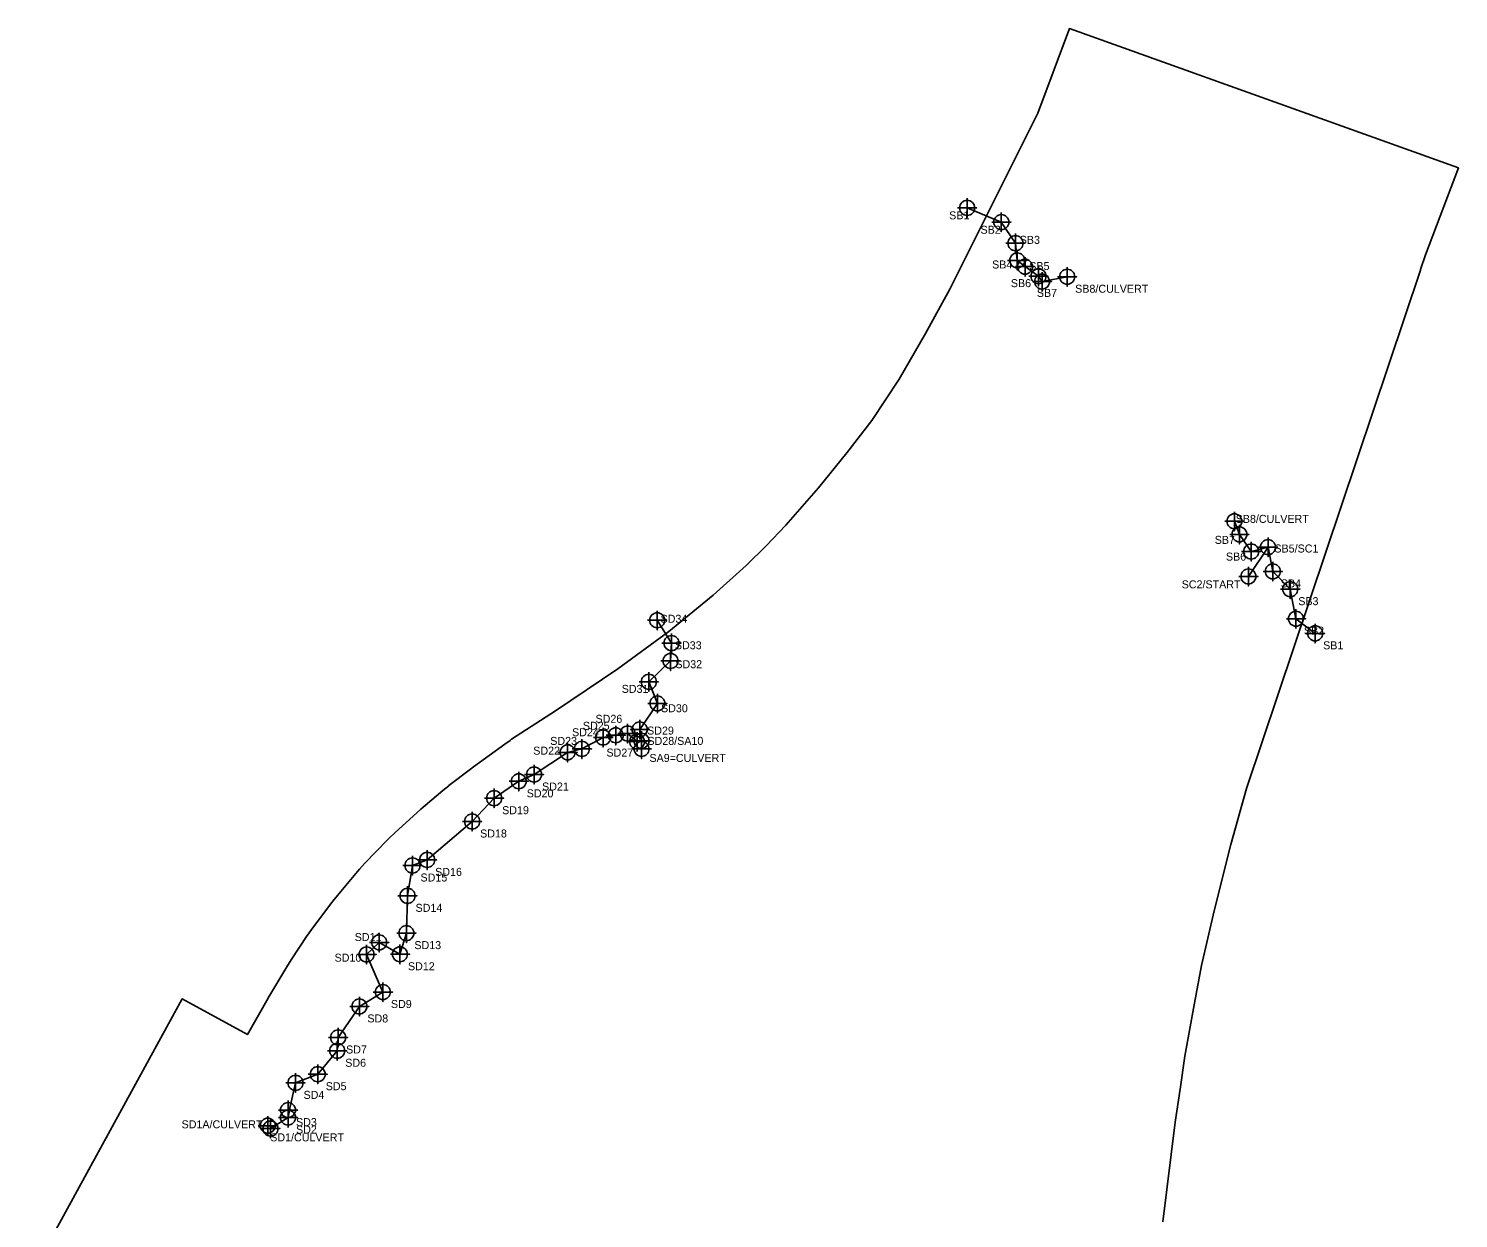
# Model space of a CAD drawing. Extents: x 2074690 to 2076562, y 742141 to 745115.
# Drawn here: x 2074775 to 2076562, y 743628 to 745115 of the extents above; entities that cross this region are included whole.
import ezdxf

# ---------------------------------------------------------------- set-up
doc = ezdxf.new("R2010")
doc.units = 0
for name, color, linetype in [('Default', 7, 'Continuous'), ('Exist Hydro Jurisdictional Stream or Body of Water Mitigable', 7, 'Continuous'), ('Exist Hydro Jurisdictional Stream or Body of Water Mitigable Cogo Comment', 7, 'Continuous'), ('Exist Hydro Jurisdictional Stream or Body of Water Mitigable Cogo Point CELL', 7, 'Continuous')]:
    doc.layers.add(name, color=color, linetype=linetype)

msp = doc.modelspace()

# ---------------------------------------------------------------- linework, layer by layer
at = {"layer": 'Default'}
msp.add_lwpolyline([(2074774.6, 743551.4), (2074966.7, 743902.2), (2075048, 743857.7), (2075048.2, 743858), (2075073.9, 743903.4), (2075074.6, 743904.6), (2075076, 743906.9), (2075097.2, 743942.5), (2075102.6, 743951.1), (2075122.9, 743981.6), (2075123, 743981.8), (2075129.3, 743990.7), (2075153.5, 744022.9), (2075154.8, 744024.6), (2075160.5, 744031.7), (2075185.5, 744061.4), (2075188.1, 744064.4), (2075195, 744071.8), (2075223.3, 744101), (2075225.4, 744103.1), (2075232.3, 744109.7), (2075264.9, 744139.3), (2075267.6, 744141.7), (2075270.2, 744144), (2075292.3, 744162.7), (2075299.7, 744168.6), (2075299.9, 744168.8), (2075327, 744189.5), (2075330.8, 744192.4), (2075369.8, 744220.8), (2075376.4, 744225.4), (2075378.3, 744226.7), (2075433, 744262.3), (2075511.1, 744314.7), (2075574.7, 744361.4), (2075630.3, 744406.7), (2075671.5, 744443.9), (2075696.4, 744468.4), (2075720.9, 744494.3), (2075762, 744541), (2075797.4, 744584.5), (2075828.3, 744624.9), (2075862.6, 744676.8), (2075895.5, 744733.6), (2075926, 744789.2), (2076035.8, 745009.1), (2076075.4, 745114.8), (2076561.5, 744940.7), (2076520.4, 744832.2), (2076514.2, 744813.8), (2076514, 744813.1), (2076296.7, 744165.4), (2076277.1, 744095.1), (2076256.5, 744012.5), (2076240.6, 743944.2), (2076230.6, 743890.5), (2076219.8, 743830.7), (2076213.7, 743789.4), (2076207.6, 743748.1), (2076192, 743623.9)], dxfattribs=at)
at = {"layer": 'Exist Hydro Jurisdictional Stream or Body of Water Mitigable'}
for points in [[(2075947.6, 744890.7), (2075990.3, 744872.9), (2076008, 744846.6), (2076010.2, 744825.1), (2076019.9, 744817.3), (2076036.8, 744805.3), (2076041.2, 744798.6), (2076072.6, 744804.7)], [(2076281.6, 744499.1), (2076287.8, 744482.8), (2076302.6, 744461.3), (2076323.6, 744466.8), (2076329.6, 744436.5), (2076351.4, 744414.3), (2076358.5, 744377.4), (2076382.5, 744359.1)], [(2076323.6, 744466.8), (2076299.1, 744430.2)], [(2075076.9, 743740.3), (2075098.8, 743754), (2075101.6, 743767.8), (2075108.2, 743797.4), (2075135.9, 743808.2), (2075160.3, 743837.5), (2075161.4, 743854.1), (2075188, 743892.9), (2075217.4, 743910.9), (2075197, 743957.8), (2075212.8, 743972.9), (2075238.7, 743958.1), (2075246.7, 743984.5), (2075248.2, 744031.1), (2075254.4, 744069), (2075272.7, 744076), (2075328.9, 744124), (2075356.4, 744153.1), (2075387.1, 744174.2), (2075406.3, 744182.7), (2075448.2, 744210.4), (2075466.1, 744214.7), (2075492.6, 744229), (2075508.4, 744231.7), (2075523.2, 744233.9), (2075535, 744223.8), (2075540.5, 744224.8), (2075538.3, 744239), (2075560.4, 744271.6), (2075549.8, 744298.5), (2075576.9, 744324.6), (2075578.1, 744346.9), (2075560.2, 744375.4)], [(2075540.5, 744224.8), (2075540.7, 744214.6)]]:
    msp.add_lwpolyline(points, dxfattribs=at)
at = {"layer": 'Exist Hydro Jurisdictional Stream or Body of Water Mitigable Cogo Point CELL'}
for points in [[(2075947.6, 744902.7), (2075947.6, 744878.7), (2075947.6, 744890.7), (2075959.6, 744890.7), (2075935.6, 744890.7)], [(2075990.3, 744884.9), (2075990.3, 744860.9), (2075990.3, 744872.9), (2076002.3, 744872.9), (2075978.3, 744872.9)], [(2076008, 744858.6), (2076008, 744834.6), (2076008, 744846.6), (2076020, 744846.6), (2075996, 744846.6)], [(2076010.2, 744837.1), (2076010.2, 744813.1), (2076010.2, 744825.1), (2076022.2, 744825.1), (2075998.2, 744825.1)], [(2076019.9, 744829.3), (2076019.9, 744805.3), (2076019.9, 744817.3), (2076031.9, 744817.3), (2076007.9, 744817.3)], [(2076036.8, 744817.3), (2076036.8, 744793.3), (2076036.8, 744805.3), (2076048.8, 744805.3), (2076024.8, 744805.3)], [(2076072.6, 744816.7), (2076072.6, 744792.7), (2076072.6, 744804.7), (2076084.6, 744804.7), (2076060.6, 744804.7)], [(2076041.2, 744810.6), (2076041.2, 744786.6), (2076041.2, 744798.6), (2076053.2, 744798.6), (2076029.2, 744798.6)], [(2076281.6, 744511.1), (2076281.6, 744487.1), (2076281.6, 744499.1), (2076293.6, 744499.1), (2076269.6, 744499.1)], [(2076287.8, 744494.8), (2076287.8, 744470.8), (2076287.8, 744482.8), (2076299.8, 744482.8), (2076275.8, 744482.8)], [(2076302.6, 744473.3), (2076302.6, 744449.3), (2076302.6, 744461.3), (2076314.6, 744461.3), (2076290.6, 744461.3)], [(2076323.6, 744478.8), (2076323.6, 744454.8), (2076323.6, 744466.8), (2076335.6, 744466.8), (2076311.6, 744466.8)], [(2076299.1, 744442.2), (2076299.1, 744418.2), (2076299.1, 744430.2), (2076311.1, 744430.2), (2076287.1, 744430.2)], [(2076329.6, 744448.5), (2076329.6, 744424.5), (2076329.6, 744436.5), (2076341.6, 744436.5), (2076317.6, 744436.5)], [(2076351.4, 744426.3), (2076351.4, 744402.3), (2076351.4, 744414.3), (2076363.4, 744414.3), (2076339.4, 744414.3)], [(2075560.2, 744387.4), (2075560.2, 744363.4), (2075560.2, 744375.4), (2075572.2, 744375.4), (2075548.2, 744375.4)], [(2076358.5, 744389.4), (2076358.5, 744365.4), (2076358.5, 744377.4), (2076370.5, 744377.4), (2076346.5, 744377.4)], [(2076382.5, 744371.1), (2076382.5, 744347.1), (2076382.5, 744359.1), (2076394.5, 744359.1), (2076370.5, 744359.1)], [(2075578.1, 744358.9), (2075578.1, 744334.9), (2075578.1, 744346.9), (2075590.1, 744346.9), (2075566.1, 744346.9)], [(2075576.9, 744336.6), (2075576.9, 744312.6), (2075576.9, 744324.6), (2075588.9, 744324.6), (2075564.9, 744324.6)], [(2075549.8, 744310.5), (2075549.8, 744286.5), (2075549.8, 744298.5), (2075561.8, 744298.5), (2075537.8, 744298.5)], [(2075560.4, 744283.6), (2075560.4, 744259.6), (2075560.4, 744271.6), (2075572.4, 744271.6), (2075548.4, 744271.6)], [(2075492.6, 744241), (2075492.6, 744217), (2075492.6, 744229), (2075504.6, 744229), (2075480.6, 744229)], [(2075508.4, 744243.7), (2075508.4, 744219.7), (2075508.4, 744231.7), (2075520.4, 744231.7), (2075496.4, 744231.7)], [(2075523.2, 744245.9), (2075523.2, 744221.9), (2075523.2, 744233.9), (2075535.2, 744233.9), (2075511.2, 744233.9)], [(2075538.3, 744251), (2075538.3, 744227), (2075538.3, 744239), (2075550.3, 744239), (2075526.3, 744239)], [(2075448.2, 744222.4), (2075448.2, 744198.4), (2075448.2, 744210.4), (2075460.2, 744210.4), (2075436.2, 744210.4)], [(2075466.1, 744226.7), (2075466.1, 744202.7), (2075466.1, 744214.7), (2075478.1, 744214.7), (2075454.1, 744214.7)], [(2075535, 744235.8), (2075535, 744211.8), (2075535, 744223.8), (2075547, 744223.8), (2075523, 744223.8)], [(2075540.5, 744236.8), (2075540.5, 744212.8), (2075540.5, 744224.8), (2075552.5, 744224.8), (2075528.5, 744224.8)], [(2075540.7, 744226.6), (2075540.7, 744202.6), (2075540.7, 744214.6), (2075552.7, 744214.6), (2075528.7, 744214.6)], [(2075387.1, 744186.2), (2075387.1, 744162.2), (2075387.1, 744174.2), (2075399.1, 744174.2), (2075375.1, 744174.2)], [(2075406.3, 744194.7), (2075406.3, 744170.7), (2075406.3, 744182.7), (2075418.3, 744182.7), (2075394.3, 744182.7)], [(2075356.4, 744165.1), (2075356.4, 744141.1), (2075356.4, 744153.1), (2075368.4, 744153.1), (2075344.4, 744153.1)], [(2075328.9, 744136), (2075328.9, 744112), (2075328.9, 744124), (2075340.9, 744124), (2075316.9, 744124)], [(2075254.4, 744081), (2075254.4, 744057), (2075254.4, 744069), (2075266.4, 744069), (2075242.4, 744069)], [(2075272.7, 744088), (2075272.7, 744064), (2075272.7, 744076), (2075284.7, 744076), (2075260.7, 744076)], [(2075248.2, 744043.1), (2075248.2, 744019.1), (2075248.2, 744031.1), (2075260.2, 744031.1), (2075236.2, 744031.1)], [(2075246.7, 743996.5), (2075246.7, 743972.5), (2075246.7, 743984.5), (2075258.7, 743984.5), (2075234.7, 743984.5)], [(2075212.8, 743984.9), (2075212.8, 743960.9), (2075212.8, 743972.9), (2075224.8, 743972.9), (2075200.8, 743972.9)], [(2075197, 743969.8), (2075197, 743945.8), (2075197, 743957.8), (2075209, 743957.8), (2075185, 743957.8)], [(2075238.7, 743970.1), (2075238.7, 743946.1), (2075238.7, 743958.1), (2075250.7, 743958.1), (2075226.7, 743958.1)], [(2075217.4, 743922.9), (2075217.4, 743898.9), (2075217.4, 743910.9), (2075229.4, 743910.9), (2075205.4, 743910.9)], [(2075188, 743904.9), (2075188, 743880.9), (2075188, 743892.9), (2075200, 743892.9), (2075176, 743892.9)], [(2075161.4, 743866.1), (2075161.4, 743842.1), (2075161.4, 743854.1), (2075173.4, 743854.1), (2075149.4, 743854.1)], [(2075160.3, 743849.5), (2075160.3, 743825.5), (2075160.3, 743837.5), (2075172.3, 743837.5), (2075148.3, 743837.5)], [(2075135.9, 743820.2), (2075135.9, 743796.2), (2075135.9, 743808.2), (2075147.9, 743808.2), (2075123.9, 743808.2)], [(2075108.2, 743809.4), (2075108.2, 743785.4), (2075108.2, 743797.4), (2075120.2, 743797.4), (2075096.2, 743797.4)], [(2075098.8, 743775.4), (2075098.8, 743751.4), (2075098.8, 743763.4), (2075110.8, 743763.4), (2075086.8, 743763.4)], [(2075098.8, 743766), (2075098.8, 743742), (2075098.8, 743754), (2075110.8, 743754), (2075086.8, 743754)], [(2075073.5, 743755.9), (2075073.5, 743731.9), (2075073.5, 743743.9), (2075085.5, 743743.9), (2075061.5, 743743.9)], [(2075076.9, 743752.3), (2075076.9, 743728.3), (2075076.9, 743740.3), (2075088.9, 743740.3), (2075064.9, 743740.3)]]:
    msp.add_lwpolyline(points, dxfattribs=at)
for centre in [(2075947.6, 744890.7), (2075990.3, 744872.9), (2076008, 744846.6), (2076010.2, 744825.1), (2076019.9, 744817.3), (2076036.8, 744805.3), (2076072.6, 744804.7), (2076041.2, 744798.6), (2076281.6, 744499.1), (2076287.8, 744482.8), (2076323.6, 744466.8), (2076302.6, 744461.3), (2076299.1, 744430.2), (2076329.6, 744436.5), (2076351.4, 744414.3), (2075560.2, 744375.4), (2076358.5, 744377.4), (2076382.5, 744359.1), (2075578.1, 744346.9), (2075576.9, 744324.6), (2075549.8, 744298.5), (2075560.4, 744271.6), (2075508.4, 744231.7), (2075523.2, 744233.9), (2075538.3, 744239), (2075466.1, 744214.7), (2075492.6, 744229), (2075535, 744223.8), (2075540.5, 744224.8), (2075540.7, 744214.6), (2075448.2, 744210.4), (2075406.3, 744182.7), (2075387.1, 744174.2), (2075356.4, 744153.1), (2075328.9, 744124), (2075254.4, 744069), (2075272.7, 744076), (2075248.2, 744031.1), (2075246.7, 743984.5), (2075212.8, 743972.9), (2075197, 743957.8), (2075238.7, 743958.1), (2075217.4, 743910.9), (2075188, 743892.9), (2075160.3, 743837.5), (2075161.4, 743854.1), (2075135.9, 743808.2), (2075108.2, 743797.4), (2075098.8, 743763.4), (2075098.8, 743754), (2075073.5, 743743.9), (2075076.9, 743740.3)]:
    msp.add_circle(centre, 9.38, dxfattribs=at)

# ---------------------------------------------------------------- texts
at = {"layer": 'Exist Hydro Jurisdictional Stream or Body of Water Mitigable Cogo Comment'}
for s, p in [('SB1', (2075925.1, 744876.4)), ('SB2', (2075964.3, 744858.4)), ('SB3', (2076013.3, 744845.8)), ('SB4', (2075978.8, 744815)), ('SB5', (2076025.2, 744813.1)), ('SB6', (2076002.2, 744791.7)), ('SB8/CULVERT', (2076082.6, 744784.7)), ('SB7', (2076034.7, 744779.5)), ('SB8/CULVERT', (2076283.2, 744497.1)), ('SB7', (2076257, 744470.9)), ('SB6', (2076271, 744450)), ('SB5/SC1', (2076331.6, 744460.1)), ('SC2/START', (2076215.7, 744415.3)), ('SB4', (2076339.6, 744416.5)), ('SB3', (2076361.4, 744394.3)), ('SD34', (2075564.4, 744372.3)), ('SB2', (2076368.5, 744357.4)), ('SD33', (2075582.3, 744339.2)), ('SB1', (2076392.5, 744339.1)), ('SD32', (2075582.9, 744315.5)), ('SD31', (2075515.8, 744284.7)), ('SD26', (2075483.1, 744247.3)), ('SD30', (2075565, 744260.5)), ('SD24', (2075453.8, 744230.5)), ('SD25', (2075467.3, 744238.6)), ('SD29', (2075547.6, 744232.6)), ('SD23', (2075426.5, 744219.7)), ('SD28/SA10', (2075548, 744219.7)), ('SD22', (2075405.3, 744207.5)), ('SD27', (2075496.8, 744205.1)), ('SA9=CULVERT', (2075550.5, 744198.4)), ('SD21', (2075416.3, 744162.7)), ('SD20', (2075397.1, 744154.2)), ('SD19', (2075366.4, 744133.1)), ('SD18', (2075338.9, 744104)), ('SD16', (2075282.7, 744056)), ('SD15', (2075264.4, 744049)), ('SD14', (2075258.2, 744011.1)), ('SD11', (2075182.1, 743974.6)), ('SD13', (2075256.7, 743964.5)), ('SD10', (2075157, 743948.8)), ('SD12', (2075248.7, 743938.1)), ('SD9', (2075227.4, 743890.9)), ('SD8', (2075198, 743872.9)), ('SD7', (2075171.4, 743834.1)), ('SD6', (2075170.3, 743817.5)), ('SD5', (2075145.9, 743788.2)), ('SD4', (2075118.2, 743777.4)), ('SD1A/CULVERT', (2074965.8, 743740.6)), ('SD3', (2075108.8, 743743.4)), ('SD2', (2075108.8, 743734)), ('SD1/CULVERT', (2075076.6, 743724.3))]:
    msp.add_text(s, height=10, dxfattribs=at).set_placement(p)

doc.saveas('drawing.dxf')
